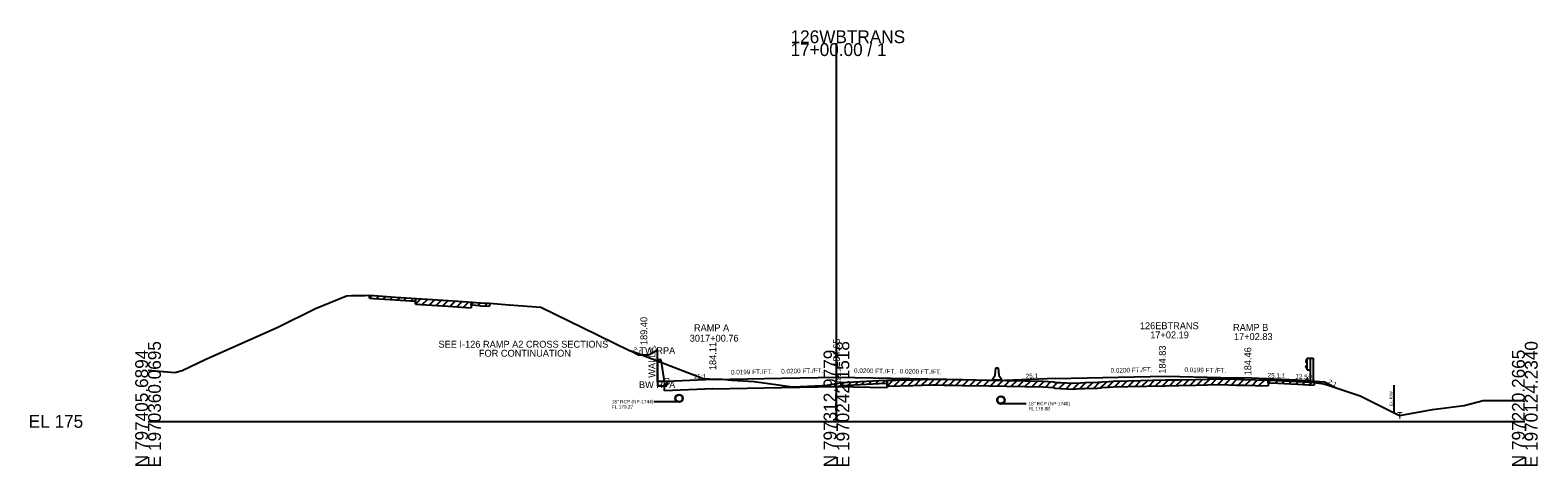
# Model space of a CAD drawing. Extents: x -6494 to 1970605, y -10 to 798140.
# Drawn here: x -25.7 to 302.8, y 9490.3 to 9585.2 of the extents above; entities that cross this region are included whole.
import ezdxf

# ---------------------------------------------------------------- set-up
doc = ezdxf.new("R2010")
doc.units = 0
for name, color, linetype in [('Default', 7, 'Continuous'), ('RD_EX_SU_Misc_TxCode', 7, 'Continuous'), ('RD_GPK_XS_Cell', 7, 'Continuous'), ('RD_Sketch1', 7, 'Continuous'), ('RD_XS_Base', 7, 'Continuous'), ('RD_XS_Box', 7, 'Continuous'), ('RD_XS_CurbTop', 7, 'Continuous'), ('RD_XS_EarthShd', 7, 'Continuous'), ('RD_XS_EwShp', 7, 'Continuous'), ('RD_XS_ExGround', 7, 'Continuous'), ('RD_XS_ExPaveRet', 7, 'Continuous'), ('RD_XS_ExRW', 7, 'Continuous'), ('RD_XS_GR', 7, 'Continuous'), ('RD_XS_MedBWall', 7, 'Continuous'), ('RD_XS_Misc_Line', 7, 'Continuous'), ('RD_XS_Pave', 7, 'Continuous'), ('RD_XS_PaveOvlay', 7, 'Continuous'), ('RD_XS_PaveShd', 7, 'Continuous'), ('RD_XS_Pipe', 7, 'Continuous'), ('RD_XS_TieSlope', 7, 'Continuous'), ('RD_XS_TX_Elev_EX', 7, 'Continuous'), ('RD_XS_TX_Elev_PR', 7, 'Continuous'), ('RD_XS_TX_Misc', 7, 'Continuous'), ('RD_XS_TX_Notes', 7, 'Continuous'), ('RD_XS_TX_Profile', 7, 'Continuous'), ('RD_XS_TX_ShdSlope', 7, 'Continuous'), ('RD_XS_TX_Slope', 7, 'Continuous'), ('RD_XS_TX_Station', 7, 'Continuous')]:
    doc.layers.add(name, color=color, linetype=linetype)

msp = doc.modelspace()

# ---------------------------------------------------------------- linework, layer by layer
at = {"layer": 'Default'}
for p, q in [((184.58, 9510.05), (184.75, 9511.63)), ((184.75, 9511.63), (185.25, 9511.63)), ((185.25, 9511.63), (185.42, 9510.05)), ((184, 9509.22), (184.58, 9510.05)), ((184, 9508.97), (184, 9509.22)), ((186, 9508.97), (184, 9508.97)), ((185.42, 9510.05), (186, 9509.22)), ((186, 9509.22), (186, 9508.97))]:
    msp.add_line(p, q, dxfattribs=at)
at = {"layer": 'RD_GPK_XS_Cell'}
for p, q in [((150, 9500), (150, 9582.39)), ((0, 9500), (150, 9500)), ((150, 9500), (300, 9500))]:
    msp.add_line(p, q, dxfattribs=at)
at = {"layer": 'RD_XS_Base'}
for p, q in [((112.53, 9508.13), (113.03, 9508.15)), ((112.53, 9506.65), (112.53, 9508.13)), ((113.03, 9508.15), (113.03, 9508.71)), ((250.41, 9508.7), (250.41, 9509.06)), ((123.05, 9507.07), (112.53, 9506.65)), ((123.05, 9507.07), (138, 9507.37)), ((138, 9507.37), (150, 9507.61)), ((150, 9507.61), (161.05, 9507.39))]:
    msp.add_line(p, q, dxfattribs=at)
at = {"layer": 'RD_XS_Box'}
for p, q in [((111.03, 9508.71), (111.03, 9515.68)), ((113.03, 9508.71), (111.03, 9508.71))]:
    msp.add_line(p, q, dxfattribs=at)
at = {"layer": 'RD_XS_CurbTop'}
for p, q in [((252.29, 9508.91), (252.54, 9509.37)), ((252.29, 9508.91), (252.76, 9508.88)), ((252.76, 9508.88), (252.7, 9509.31))]:
    msp.add_line(p, q, dxfattribs=at)
msp.add_ellipse((252.61, 9509.29), major_axis=(0, -0.131), ratio=0.686, start_param=1.762783, end_param=4.036677, dxfattribs=at)
at = {"layer": 'RD_XS_EarthShd'}
msp.add_line((250.41, 9509.06), (252.42, 9508.9), dxfattribs=at)
at = {"layer": 'RD_XS_ExGround'}
msp.add_lwpolyline([(0, 9511.17), (3.34, 9510.87), (5.86, 9510.66), (7.41, 9511.1), (12.44, 9513.45), (28.27, 9520.52), (36.48, 9524.56), (43.21, 9527.36), (44.35, 9527.39), (47.26, 9527.44), (48.26, 9527.46), (49.19, 9527.4), (53.91, 9527.07), (65.36, 9526.32), (70.67, 9525.97), (72.12, 9525.85), (72.5, 9525.83), (74.37, 9525.73), (78.65, 9525.42), (85.61, 9524.9), (97.8, 9518.89), (102.08, 9516.79), (104.45, 9515.68), (104.93, 9515.44), (106.29, 9514.99), (108.87, 9514.01), (121.21, 9509.27), (122.3, 9509.29), (125.08, 9509.18), (127.21, 9508.98), (132.04, 9508.66), (134.66, 9508.29), (140.4, 9507.54), (146.86, 9507.78), (147.62, 9507.8), (148.81, 9508.02), (150, 9508.24), (151.05, 9508.43), (159.33, 9508.91), (166.68, 9509.04), (170.9, 9509.17), (171.52, 9509.18), (173.43, 9509.16), (175.4, 9509.13), (177.5, 9509.09), (183.2, 9508.98), (195.01, 9508.74), (197.38, 9508.62), (197.67, 9508.5), (198.86, 9508.44), (201.43, 9508.29), (203.15, 9508.41), (204.11, 9508.44), (206.91, 9508.51), (207.64, 9508.54), (207.91, 9508.64), (209.4, 9508.71), (210.28, 9508.75), (213.49, 9508.82), (221.72, 9509.01), (224.59, 9509.06), (228.32, 9509.13), (230.82, 9509.19), (233.77, 9509.26), (237.15, 9509.16), (238.83, 9509.12), (241.28, 9509.05), (246.17, 9508.93), (250.49, 9508.7), (254.08, 9508.5), (255.7, 9508.24), (256.74, 9508.05), (258.69, 9507.4), (264.14, 9505.57), (270.07, 9502.56), (272.7, 9501.27), (279.52, 9502.5), (279.85, 9502.57), (286.76, 9503.47), (290.96, 9504.52), (297.52, 9504.52), (299.54, 9504.52), (300, 9504.36)], dxfattribs=at)
at = {"layer": 'RD_XS_ExPaveRet'}
for p, q in [((48.26, 9526.84), (48.26, 9527.46)), ((48.26, 9526.84), (49.19, 9526.77)), ((49.19, 9526.77), (53.91, 9526.44)), ((53.91, 9526.44), (58.26, 9526.16)), ((58.26, 9525.53), (58.26, 9526.78)), ((58.26, 9526.78), (58.26, 9526.16)), ((58.26, 9525.53), (65.36, 9525.07)), ((65.36, 9525.07), (70.37, 9524.74)), ((70.37, 9525.99), (70.37, 9524.74)), ((70.37, 9525.37), (70.37, 9525.99)), ((70.37, 9525.37), (70.67, 9525.35)), ((70.67, 9525.35), (72.12, 9525.22)), ((72.12, 9525.22), (72.5, 9525.2)), ((72.5, 9525.2), (74.37, 9525.1)), ((74.37, 9525.73), (74.37, 9525.1)), ((151.05, 9507.81), (151.05, 9508.43)), ((151.05, 9507.81), (159.33, 9508.28)), ((159.33, 9508.28), (161.05, 9508.31)), ((161.05, 9507.69), (161.05, 9508.94)), ((161.05, 9508.94), (161.05, 9508.31)), ((161.05, 9507.69), (166.68, 9507.79)), ((166.68, 9507.79), (170.9, 9507.92)), ((170.9, 9507.92), (171.52, 9507.93)), ((171.52, 9507.93), (173.43, 9507.91)), ((173.43, 9507.91), (175.4, 9507.88)), ((175.4, 9507.88), (177.5, 9507.84)), ((177.5, 9507.84), (183.2, 9507.73)), ((213.49, 9507.57), (221.72, 9507.76)), ((221.72, 9507.76), (224.59, 9507.81)), ((224.59, 9507.81), (228.32, 9507.88)), ((228.32, 9507.88), (230.82, 9507.94)), ((230.82, 9507.94), (233.77, 9508.01)), ((233.77, 9508.01), (237.15, 9507.91)), ((237.15, 9507.91), (238.83, 9507.87)), ((238.83, 9507.87), (241.28, 9507.8)), ((241.28, 9507.8), (244.07, 9507.73)), ((244.07, 9508.98), (244.07, 9507.73)), ((244.07, 9508.36), (244.07, 9508.98)), ((244.07, 9508.36), (246.17, 9508.3)), ((246.17, 9508.3), (250.49, 9508.08)), ((250.49, 9508.08), (254.08, 9507.88)), ((254.08, 9508.5), (254.08, 9507.88)), ((183.2, 9507.73), (195.01, 9507.49)), ((195.01, 9507.49), (197.38, 9507.37)), ((197.38, 9507.37), (197.67, 9507.25)), ((197.67, 9507.25), (198.86, 9507.19)), ((198.86, 9507.19), (201.43, 9507.04)), ((201.43, 9507.04), (203.15, 9507.16)), ((203.15, 9507.16), (204.11, 9507.19)), ((204.11, 9507.19), (206.91, 9507.26)), ((206.91, 9507.26), (207.64, 9507.29)), ((207.64, 9507.29), (207.91, 9507.39)), ((207.91, 9507.39), (209.4, 9507.46)), ((209.4, 9507.46), (210.28, 9507.5)), ((210.28, 9507.5), (213.49, 9507.57))]:
    msp.add_line(p, q, dxfattribs=at)
at = {"layer": 'RD_XS_ExRW'}
msp.add_line((271.43, 9507.89), (271.43, 9501.89), dxfattribs=at)
at = {"layer": 'RD_XS_GR'}
for p, q in [((252.56, 9513.62), (252.29, 9513.18)), ((252.29, 9513.18), (252.29, 9513.07)), ((252.29, 9513.07), (252.56, 9512.63)), ((252.29, 9511.92), (252.56, 9512.36)), ((252.29, 9511.81), (252.29, 9511.92)), ((252.56, 9511.37), (252.29, 9511.81)), ((252.56, 9513.78), (253.23, 9513.78)), ((252.56, 9511.21), (252.56, 9513.78)), ((252.56, 9511.21), (253.23, 9511.21)), ((253.23, 9513.78), (253.9, 9513.78)), ((253.23, 9513.78), (253.23, 9508.83)), ((253.9, 9513.78), (253.9, 9508.72))]:
    msp.add_line(p, q, dxfattribs=at)
at = {"layer": 'RD_XS_MedBWall'}
for p, q in [((111.78, 9513.38), (111.03, 9513.38)), ((111.03, 9513.38), (111.03, 9507.71)), ((112.53, 9508.71), (111.78, 9513.38)), ((113.03, 9508.71), (112.53, 9508.71)), ((113.03, 9507.71), (113.03, 9508.71)), ((111.03, 9507.71), (113.03, 9507.71))]:
    msp.add_line(p, q, dxfattribs=at)
at = {"layer": 'RD_XS_Misc_Line'}
for p, q in [((48.26, 9526.84), (48.84, 9527.42)), ((49.76, 9526.73), (50.34, 9527.32)), ((51.26, 9526.63), (51.84, 9527.21)), ((52.76, 9526.52), (53.34, 9527.11)), ((54.26, 9526.42), (54.84, 9527.01)), ((55.76, 9526.32), (56.34, 9526.91)), ((57.26, 9526.22), (57.84, 9526.81)), ((58.26, 9525.53), (59.43, 9526.71)), ((59.76, 9525.44), (60.93, 9526.61)), ((61.26, 9525.34), (62.43, 9526.51)), ((62.76, 9525.24), (63.93, 9526.41)), ((64.26, 9525.14), (65.43, 9526.32)), ((65.76, 9525.04), (66.93, 9526.22)), ((67.26, 9524.95), (68.43, 9526.12)), ((68.76, 9524.85), (69.93, 9526.02)), ((70.37, 9525.37), (70.95, 9525.95)), ((71.87, 9525.25), (72.45, 9525.83)), ((73.37, 9525.16), (73.96, 9525.75)), ((151.05, 9507.81), (151.71, 9508.47)), ((152.55, 9507.9), (153.21, 9508.56)), ((154.05, 9507.98), (154.71, 9508.64)), ((155.55, 9508.07), (156.21, 9508.73)), ((157.05, 9508.15), (157.71, 9508.81)), ((158.55, 9508.24), (159.21, 9508.9)), ((160.05, 9508.29), (160.69, 9508.93)), ((161.05, 9507.69), (162.33, 9508.96)), ((162.55, 9507.71), (163.83, 9508.99)), ((164.05, 9507.74), (165.33, 9509.01)), ((165.55, 9507.77), (166.83, 9509.04)), ((167.05, 9507.8), (168.34, 9509.09)), ((168.55, 9507.85), (169.84, 9509.14)), ((170.05, 9507.89), (171.34, 9509.18)), ((171.55, 9507.93), (172.79, 9509.17)), ((173.05, 9507.91), (174.29, 9509.14)), ((174.55, 9507.89), (175.78, 9509.12)), ((176.05, 9507.86), (177.28, 9509.09)), ((177.55, 9507.84), (178.78, 9509.07)), ((179.05, 9507.81), (180.28, 9509.04)), ((180.55, 9507.78), (181.78, 9509.01)), ((182.05, 9507.75), (183.28, 9508.98)), ((183.55, 9507.73), (184.78, 9508.95)), ((185.05, 9507.69), (186.28, 9508.92)), ((186.55, 9507.66), (187.78, 9508.89)), ((188.05, 9507.63), (189.28, 9508.86)), ((189.55, 9507.6), (190.78, 9508.82)), ((191.05, 9507.57), (192.28, 9508.79)), ((192.55, 9507.54), (193.78, 9508.76)), ((194.06, 9507.51), (195.27, 9508.72)), ((195.56, 9507.46), (196.75, 9508.65)), ((197.06, 9507.38), (198.15, 9508.47)), ((198.56, 9507.2), (199.74, 9508.39)), ((200.06, 9507.12), (201.24, 9508.3)), ((201.56, 9507.05), (202.9, 9508.39)), ((203.06, 9507.15), (204.35, 9508.44)), ((204.56, 9507.2), (205.84, 9508.48)), ((206.06, 9507.24), (207.35, 9508.53)), ((207.56, 9507.29), (208.96, 9508.69)), ((209.06, 9507.44), (210.36, 9508.75)), ((210.56, 9507.51), (211.83, 9508.79)), ((212.06, 9507.54), (213.33, 9508.82)), ((213.56, 9507.57), (214.83, 9508.85)), ((215.06, 9507.61), (216.34, 9508.88)), ((216.56, 9507.64), (217.84, 9508.92)), ((218.06, 9507.67), (219.34, 9508.95)), ((219.56, 9507.71), (220.84, 9508.99)), ((221.06, 9507.74), (222.33, 9509.02)), ((222.56, 9507.77), (223.83, 9509.05)), ((224.06, 9507.8), (225.33, 9509.07)), ((225.56, 9507.83), (226.83, 9509.1)), ((227.06, 9507.86), (228.33, 9509.13)), ((228.56, 9507.89), (229.84, 9509.17)), ((230.06, 9507.92), (231.34, 9509.21)), ((231.56, 9507.96), (232.84, 9509.24)), ((233.06, 9507.99), (234.31, 9509.24)), ((234.56, 9507.99), (235.77, 9509.2)), ((236.06, 9507.94), (237.27, 9509.16)), ((237.56, 9507.9), (238.78, 9509.12)), ((239.06, 9507.87), (240.27, 9509.08)), ((240.56, 9507.82), (241.77, 9509.04)), ((242.06, 9507.78), (243.28, 9509)), ((244.07, 9508.36), (244.68, 9508.97)), ((245.57, 9508.32), (246.18, 9508.93)), ((247.07, 9508.26), (247.67, 9508.85)), ((248.57, 9508.18), (249.17, 9508.77)), ((250.07, 9508.1), (250.67, 9508.69)), ((251.57, 9508.02), (252.16, 9508.61)), ((253.07, 9507.93), (253.66, 9508.53))]:
    msp.add_line(p, q, dxfattribs=at)
at = {"layer": 'RD_XS_Pave'}
for p, q in [((123.05, 9509.11), (138, 9509.41)), ((138, 9509.41), (150, 9509.65)), ((150, 9509.65), (174, 9509.17)), ((197.77, 9509.35), (221.77, 9509.83)), ((221.77, 9509.83), (233.77, 9509.59)), ((233.77, 9509.59), (240.39, 9509.46))]:
    msp.add_line(p, q, dxfattribs=at)
at = {"layer": 'RD_XS_PaveOvlay'}
for p, q in [((161.05, 9508.94), (166.68, 9509.04)), ((161.05, 9508.94), (161.05, 9507.39)), ((166.68, 9509.04), (170.9, 9509.17)), ((170.9, 9509.17), (171.52, 9509.18)), ((171.52, 9509.18), (173.43, 9509.16)), ((173.43, 9509.16), (175.4, 9509.13)), ((175.4, 9509.13), (177.5, 9509.09)), ((177.5, 9509.09), (183.2, 9508.98)), ((183.2, 9508.98), (195.01, 9508.74)), ((195.01, 9508.74), (197.38, 9508.62)), ((197.38, 9508.62), (197.67, 9508.5)), ((197.67, 9508.5), (198.86, 9508.44)), ((198.86, 9508.44), (201.43, 9508.29)), ((201.43, 9508.29), (203.15, 9508.41)), ((203.15, 9508.41), (204.11, 9508.44)), ((204.11, 9508.44), (206.91, 9508.51)), ((206.91, 9508.51), (207.64, 9508.54)), ((207.64, 9508.54), (207.91, 9508.64)), ((207.91, 9508.64), (209.4, 9508.71)), ((209.4, 9508.71), (210.28, 9508.75)), ((210.28, 9508.75), (213.49, 9508.82)), ((213.49, 9508.82), (221.72, 9509.01)), ((221.72, 9509.01), (224.59, 9509.06)), ((224.59, 9509.06), (228.32, 9509.13)), ((228.32, 9509.13), (230.82, 9509.19)), ((230.82, 9509.19), (233.77, 9509.26)), ((233.77, 9509.26), (237.15, 9509.16)), ((237.15, 9509.16), (238.83, 9509.12)), ((238.83, 9509.12), (241.28, 9509.05)), ((241.28, 9509.05), (244.07, 9508.98)), ((244.07, 9508.98), (246.17, 9508.93)), ((246.17, 9508.93), (250.41, 9508.7))]:
    msp.add_line(p, q, dxfattribs=at)
at = {"layer": 'RD_XS_PaveShd'}
for p, q in [((123.05, 9509.11), (113.03, 9508.71)), ((174, 9509.17), (186.68, 9508.91)), ((197.77, 9509.35), (186.68, 9508.91)), ((240.39, 9509.46), (250.41, 9509.06))]:
    msp.add_line(p, q, dxfattribs=at)
at = {"layer": 'RD_XS_Pipe'}
for p, q in [((115.2, 9504.27), (110.2, 9504.27)), ((186.34, 9503.88), (191.34, 9503.88))]:
    msp.add_line(p, q, dxfattribs=at)
for centre, radius in [((115.7, 9505.02), 0.85), ((115.7, 9505.02), 0.75), ((185.84, 9504.63), 0.85), ((185.84, 9504.63), 0.75)]:
    msp.add_circle(centre, radius, dxfattribs=at)
at = {"layer": 'RD_XS_TieSlope'}
for p, q in [((105.03, 9515.4), (107.03, 9514.4)), ((109.03, 9514.4), (107.03, 9514.4)), ((111.03, 9515.4), (109.03, 9514.4)), ((252.42, 9508.9), (256.17, 9508.6)), ((258.34, 9507.51), (256.17, 9508.6))]:
    msp.add_line(p, q, dxfattribs=at)

# ---------------------------------------------------------------- texts
at = {"layer": 'RD_EX_SU_Misc_TxCode'}
msp.add_text('G', height=1.5, dxfattribs=at).set_placement((112.28, 9507.96))
at = {"layer": 'RD_GPK_XS_Cell'}
for s, p in [('126WBTRANS', (140, 9582.39)), ('17+00.00 / 1', (140, 9579.59)), ('EL 175', (-26, 9498.6))]:
    msp.add_text(s, height=2.8, dxfattribs=at).set_placement(p)
for s, p in [('N 797405.6894', (0, 9490)), ('E 1970360.0695', (2.8, 9490)), ('N 797312.9779', (150, 9490)), ('E 1970242.1518', (152.8, 9490)), ('N 797220.2665', (300, 9490)), ('E 1970124.2340', (302.8, 9490))]:
    msp.add_text(s, height=2.8, rotation=90, dxfattribs=at).set_placement(p)
at = {"layer": 'RD_Sketch1'}
msp.add_text('T', height=1.5, dxfattribs=at).set_placement((272.15, 9500.52))
at = {"layer": 'RD_XS_EwShp'}
for s, p in [('TW RPA', (107.07, 9514.65)), ('BW RPA', (106.97, 9507.23))]:
    msp.add_text(s, height=1.5, dxfattribs=at).set_placement(p)
at = {"layer": 'RD_XS_ExRW'}
msp.add_text('Ex. R/W ', height=0.65, rotation=90, dxfattribs=at).set_placement((271.18, 9503.28))
at = {"layer": 'RD_XS_Pipe'}
for s, p in [('18" RCP (NP-1744)', (101.05, 9503.9)), ('FL 179.27', (101.05, 9502.77)), ('18" RCP (NP-1748)', (191.84, 9503.5)), ('FL 178.88', (191.84, 9502.38))]:
    msp.add_text(s, height=0.75, dxfattribs=at).set_placement(p)
at = {"layer": 'RD_XS_TX_Elev_EX'}
msp.add_text('183.24', height=1, rotation=90, dxfattribs=at).set_placement((151, 9508.24))
at = {"layer": 'RD_XS_TX_Elev_PR'}
for s, p in [('184.65', (150.75, 9511.9)), ('184.11', (123.8, 9511.16)), (' 184.83', (221.77, 9509.83)), (' 184.46', (240.39, 9509.46))]:
    msp.add_text(s, height=1.5, rotation=90, dxfattribs=at).set_placement(p)
at = {"layer": 'RD_XS_TX_Misc'}
msp.add_text('189.40', height=1.5, rotation=90, dxfattribs=at).set_placement((108.78, 9516.62))
at = {"layer": 'RD_XS_TX_Notes'}
for s, p in [('SEE I-126 RAMP A2 CROSS SECTIONS', (63.28, 9516.05)), ('FOR CONTINUATION', (72.09, 9514.09))]:
    msp.add_text(s, height=1.5, dxfattribs=at).set_placement(p)
msp.add_text('WALL', height=1.5, rotation=90, dxfattribs=at).set_placement((110.54, 9509.5))
at = {"layer": 'RD_XS_TX_Profile'}
for s, rotation, p in [('25:1', 2.2905, (191.25, 9509.34)), ('25.1:1', 357.7152, (243.93, 9509.57))]:
    msp.add_text(s, height=1, rotation=rotation, dxfattribs=at).set_placement(p)
at = {"layer": 'RD_XS_TX_ShdSlope'}
msp.add_text('12.5:1', height=1, rotation=355.4376, dxfattribs=at).set_placement((249.96, 9509.35))
at = {"layer": 'RD_XS_TX_Slope'}
for s, rotation, p in [('2:1', 333.4349, (105.49, 9515.38)), ('2:1', 26.5651, (109.43, 9514.92)), ('0.0199 FT./FT.', 1.1405, (127.03, 9510.19)), ('0.0200 FT./FT.', 1.1458, (137.98, 9510.41)), ('0.0200 FT./FT.', 358.8542, (153.83, 9510.58)), ('0.0200 FT./FT.', 358.8542, (163.8, 9510.44)), ('0.0200 FT./FT.', 1.1462, (209.75, 9510.59)), ('0.0199 FT./FT.', 358.8577, (225.82, 9510.75)), ('25:1', 2.2874, (118.98, 9509.2)), ('2:1', 333.4349, (257.02, 9508.34))]:
    msp.add_text(s, height=1, rotation=rotation, dxfattribs=at).set_placement(p)
at = {"layer": 'RD_XS_TX_Station'}
for s, p in [('RAMP A', (118.94, 9519.63)), ('126EBTRANS', (216.12, 9520.08)), ('RAMP B', (236.42, 9519.71)), ('3017+00.76', (118.03, 9517.36)), ('17+02.19', (218.37, 9518.08)), ('17+02.83', (236.62, 9517.71))]:
    msp.add_text(s, height=1.5, dxfattribs=at).set_placement(p)

doc.saveas('drawing.dxf')
